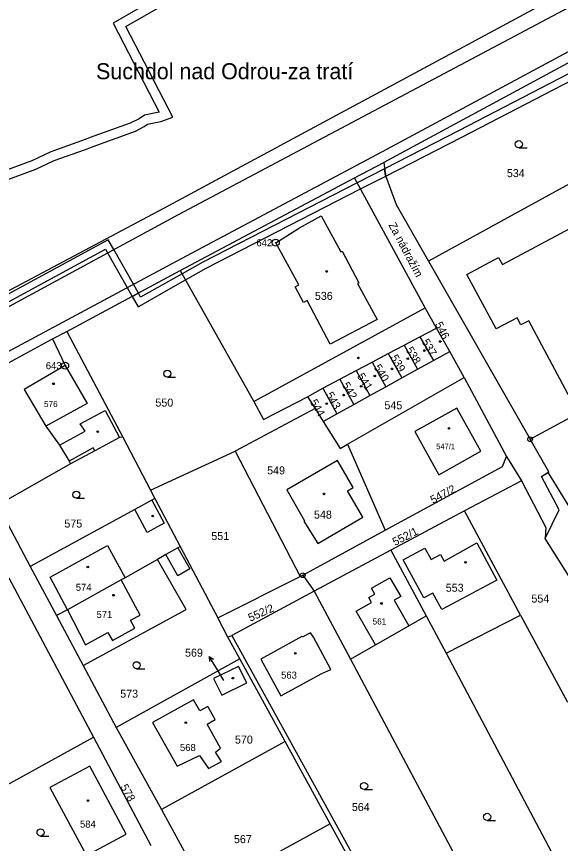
# Model space of a CAD drawing. Extents: x -504988 to -494607, y -1123820 to -1114018.
# Drawn here: x -497582.5 to -497467, y -1121208.2 to -1121032.5 of the extents above; entities that cross this region are included whole.
import ezdxf

# ---------------------------------------------------------------- set-up
doc = ezdxf.new("R2010")
doc.units = 0
for name, color, linetype in [('Hranice parcel', 7, 'Continuous'), ('Parcelní čísla', 7, 'Continuous'), ('Pop  PČ popisy', 7, 'Continuous'), ('Vnitřní kresba', 7, 'Continuous'), ('Věcná břemena k části', 7, 'Continuous'), ('Značky bodu BP', 7, 'Continuous'), ('Značky budov', 7, 'Continuous'), ('Značky kultur', 7, 'Continuous')]:
    doc.layers.add(name, color=color, linetype=linetype)

msp = doc.modelspace()

# ---------------------------------------------------------------- linework, layer by layer
at = {"layer": 'Hranice parcel'}
for p, q in [((-497444.01, -1121056.47), (-497495.04, -1121084.45)), ((-497510.73, -1121066.79), (-497504.55, -1121063.5)), ((-497547.73, -1121086.48), (-497510.73, -1121066.79)), ((-497495.04, -1121084.45), (-497473.48, -1121122.3)), ((-497571.81, -1121099.41), (-497547.73, -1121086.48)), ((-497574.88, -1121100.96), (-497571.81, -1121099.41)), ((-497571.81, -1121099.41), (-497559.93, -1121121.88)), ((-497496.86, -1121100.53), (-497493.36, -1121098.69)), ((-497490.54, -1121103.66), (-497493.36, -1121098.69)), ((-497598.99, -1121114.11), (-497574.88, -1121100.96)), ((-497500.24, -1121102.31), (-497496.86, -1121100.53)), ((-497496.86, -1121100.53), (-497494, -1121105.57)), ((-497503.59, -1121104.09), (-497500.24, -1121102.31)), ((-497500.24, -1121102.31), (-497497.36, -1121107.42)), ((-497507.03, -1121105.91), (-497503.59, -1121104.09)), ((-497503.59, -1121104.09), (-497500.68, -1121109.26)), ((-497494, -1121105.57), (-497490.54, -1121103.66)), ((-497487.47, -1121109.21), (-497490.54, -1121103.66)), ((-497510.43, -1121107.7), (-497507.03, -1121105.91)), ((-497507.03, -1121105.91), (-497504.1, -1121111.15)), ((-497497.36, -1121107.42), (-497494, -1121105.57)), ((-497513.9, -1121109.54), (-497510.43, -1121107.7)), ((-497510.43, -1121107.7), (-497507.47, -1121113.01)), ((-497500.68, -1121109.26), (-497497.36, -1121107.42)), ((-497517.5, -1121111.44), (-497513.9, -1121109.54)), ((-497513.9, -1121109.54), (-497510.91, -1121114.91)), ((-497512.23, -1121123.36), (-497487.47, -1121109.21)), ((-497504.1, -1121111.15), (-497500.68, -1121109.26)), ((-497487.47, -1121109.21), (-497478.53, -1121125.97)), ((-497520.73, -1121113.27), (-497517.5, -1121111.44)), ((-497517.5, -1121111.44), (-497514.49, -1121116.89)), ((-497507.47, -1121113.01), (-497504.1, -1121111.15)), ((-497520.73, -1121113.27), (-497519.14, -1121115.8)), ((-497510.91, -1121114.91), (-497507.47, -1121113.01)), ((-497514.49, -1121116.89), (-497510.91, -1121114.91)), ((-497519.14, -1121115.8), (-497536.09, -1121124.82)), ((-497519.14, -1121115.8), (-497517.43, -1121118.51)), ((-497517.43, -1121118.51), (-497514.49, -1121116.89)), ((-497559.93, -1121121.88), (-497554.06, -1121133.13)), ((-497512.23, -1121123.36), (-497504.22, -1121141.64)), ((-497554.06, -1121133.13), (-497536.09, -1121124.82)), ((-497536.09, -1121124.82), (-497522.28, -1121151.46)), ((-497478.53, -1121125.97), (-497475.34, -1121131.13)), ((-497571.04, -1121127.52), (-497586.5, -1121136.34)), ((-497475.34, -1121131.13), (-497487.42, -1121137.49)), ((-497554.06, -1121133.13), (-497553.13, -1121134.9)), ((-497586.5, -1121136.34), (-497579.58, -1121149.32)), ((-497553.13, -1121134.9), (-497547.79, -1121145.12)), ((-497487.42, -1121137.49), (-497503.02, -1121145.85)), ((-497475.5, -1121159.69), (-497487.42, -1121137.49)), ((-497521.76, -1121151.18), (-497504.22, -1121141.64)), ((-497547.79, -1121145.12), (-497539.75, -1121160.22)), ((-497503.02, -1121145.85), (-497519.35, -1121154.61)), ((-497503.02, -1121145.85), (-497495.55, -1121159.84)), ((-497579.58, -1121149.32), (-497574.03, -1121159.72)), ((-497584.13, -1121151.76), (-497566.16, -1121185.61)), ((-497539.75, -1121160.22), (-497522.28, -1121151.46)), ((-497522.28, -1121151.46), (-497521.76, -1121151.18)), ((-497521.76, -1121151.18), (-497519.35, -1121154.61)), ((-497519.35, -1121154.61), (-497536.83, -1121163.99)), ((-497519.35, -1121154.61), (-497511.59, -1121169.03)), ((-497574.03, -1121159.72), (-497568.35, -1121170.37)), ((-497537.66, -1121164.34), (-497539.75, -1121160.22)), ((-497495.55, -1121159.84), (-497491.31, -1121167.78)), ((-497491.31, -1121167.78), (-497475.5, -1121159.69)), ((-497475.5, -1121159.69), (-497465.57, -1121178.18)), ((-497537.66, -1121164.34), (-497536.83, -1121163.99)), ((-497535.11, -1121168.92), (-497537.66, -1121164.34)), ((-497536.83, -1121163.99), (-497482.55, -1121262.3)), ((-497491.31, -1121167.78), (-497451.07, -1121243.81)), ((-497535.11, -1121168.92), (-497561.32, -1121183.55)), ((-497525.49, -1121186.51), (-497535.11, -1121168.92)), ((-497511.59, -1121169.03), (-497467.06, -1121252.84)), ((-497568.35, -1121170.37), (-497561.32, -1121183.55)), ((-497561.32, -1121183.55), (-497551.74, -1121200.95)), ((-497592.3, -1121200.03), (-497566.16, -1121185.61)), ((-497566.16, -1121185.61), (-497554.01, -1121208.59)), ((-497525.49, -1121186.51), (-497551.74, -1121200.95)), ((-497515.91, -1121204.02), (-497525.49, -1121186.51)), ((-497551.74, -1121200.95), (-497542.24, -1121218.42)), ((-497515.91, -1121204.02), (-497542.24, -1121218.42))]:
    msp.add_line(p, q, dxfattribs=at)
for points in [[(-497161, -1120877.53), (-497162.08, -1120875.61), (-497193.91, -1120893.79), (-497205.64, -1120899.19), (-497240.26, -1120919.63), (-497250.18, -1120924.55), (-497404.22, -1121006.98), (-497504.86, -1121061.28), (-497548.64, -1121084.52), (-497630.65, -1121128.6), (-497742.3, -1121188.23), (-497831.7, -1121236.04), (-497830.39, -1121238.19)], [(-497196.93, -1120886.64), (-497265.24, -1120919.02), (-497346.92, -1120963.08), (-497519.27, -1121056.03), (-497550.25, -1121072.74), (-497642.8, -1121121.95), (-497742.1, -1121178.41), (-497789.44, -1121202.25)], [(-497454.26, -1121037.32), (-497461.19, -1121040.05), (-497504.55, -1121063.5)], [(-497504.55, -1121063.5), (-497504.17, -1121066.25), (-497501.88, -1121072.45), (-497495.04, -1121084.45)], [(-497493.36, -1121098.69), (-497495.78, -1121094.37), (-497510.73, -1121066.79)], [(-497547.73, -1121086.48), (-497532.15, -1121114.3), (-497530.1, -1121118.1), (-497520.73, -1121113.27)], [(-497574.88, -1121100.96), (-497572.18, -1121106.67), (-497580.85, -1121111.75), (-497576.29, -1121119.55), (-497573.34, -1121123.54), (-497571.34, -1121126.99), (-497571.04, -1121127.52)], [(-497473.48, -1121122.3), (-497463.27, -1121116.77), (-497446.25, -1121107.58)], [(-497483.92, -1121124.84), (-497489.04, -1121115.69), (-497497.98, -1121120.68), (-497492.86, -1121129.84), (-497483.92, -1121124.84)], [(-497517.43, -1121118.51), (-497513.81, -1121124.27), (-497512.23, -1121123.36)], [(-497559.93, -1121121.88), (-497560.62, -1121121.95), (-497565.88, -1121124.76), (-497571.04, -1121127.52)], [(-497471.07, -1121130.21), (-497469.54, -1121129.22), (-497473.48, -1121122.3)], [(-497504.22, -1121141.64), (-497479.32, -1121128.1), (-497478.53, -1121125.97)], [(-497518.55, -1121144.48), (-497508.99, -1121138.87), (-497512.24, -1121133.25), (-497511.06, -1121132.57), (-497514.37, -1121126.84), (-497525.15, -1121133.07), (-497521.35, -1121139.64), (-497521.53, -1121139.74), (-497518.55, -1121144.48)], [(-497464.35, -1121137.95), (-497465.39, -1121136.25), (-497469.57, -1121129.41), (-497471.07, -1121130.21)], [(-497475.34, -1121131.13), (-497470.16, -1121141.04), (-497470.26, -1121143.39)], [(-497470.26, -1121143.39), (-497467.32, -1121137.27), (-497471.07, -1121130.21)], [(-497553.13, -1121134.9), (-497553.81, -1121135.27), (-497557.4, -1121137.22), (-497579.58, -1121149.32)], [(-497445.11, -1121171.05), (-497458.87, -1121161.47), (-497470.26, -1121143.39)], [(-497547.79, -1121145.12), (-497548.29, -1121145.36), (-497550.81, -1121146.8), (-497552.55, -1121147.82)], [(-497552.55, -1121147.82), (-497559.42, -1121151.72), (-497560.27, -1121152.19), (-497571.67, -1121158.56), (-497574.03, -1121159.72)], [(-497568.35, -1121170.37), (-497546.52, -1121158.45), (-497552.55, -1121147.82)], [(-497511.59, -1121169.03), (-497506.27, -1121165.98), (-497499.23, -1121161.95), (-497495.55, -1121159.84)], [(-497521.86, -1121164.35), (-497521.93, -1121164.23), (-497530.67, -1121168.99), (-497526.4, -1121176.83), (-497517.66, -1121172.07), (-497515.81, -1121171.19), (-497517.49, -1121168), (-497519.49, -1121164.33), (-497520.07, -1121163.42), (-497521.86, -1121164.35)], [(-497533.64, -1121174.06), (-497535.37, -1121170.55), (-497540.66, -1121173.14), (-497538.94, -1121176.66), (-497533.64, -1121174.06)], [(-497553.64, -1121182.5), (-497548.4, -1121191.75), (-497543.67, -1121189.46), (-497541.76, -1121192.22), (-497539.02, -1121190.77), (-497540.27, -1121188.76), (-497539.19, -1121187.96), (-497542.05, -1121182.83), (-497540.31, -1121181.86), (-497541.88, -1121179.06), (-497543.62, -1121180.03), (-497544.94, -1121177.68), (-497553.64, -1121182.5)], [(-497566.97, -1121191.78), (-497575.41, -1121196.31), (-497567.65, -1121210.75), (-497559.22, -1121206.22), (-497566.97, -1121191.78)], [(-497535.87, -1121230.16), (-497509.45, -1121215.83), (-497515.91, -1121204.02)]]:
    msp.add_lwpolyline(points, dxfattribs=at)
at = {"layer": 'Pop  PČ popisy'}
for p, q in [((-497540.05, -1121170.97), (-497541.64, -1121168.43)), ((-497541.64, -1121168.43), (-497540.68, -1121169.01)), ((-497541.64, -1121168.43), (-497541.53, -1121169.54)), ((-497538.49, -1121173.53), (-497540.05, -1121170.97))]:
    msp.add_line(p, q, dxfattribs=at)
at = {"layer": 'Vnitřní kresba'}
for p, q in [((-497548.12, -1121074.56), (-497415.16, -1121003.88)), ((-497479.34, -1121085.21), (-497447.32, -1121067.97)), ((-497641.18, -1121124.99), (-497548.12, -1121074.56)), ((-497522.45, -1121077.36), (-497517.8, -1121074.86)), ((-497517.8, -1121074.86), (-497513.68, -1121082.52)), ((-497527.47, -1121080.55), (-497522.45, -1121077.36)), ((-497522.59, -1121089.51), (-497527.47, -1121080.55)), ((-497513.68, -1121082.52), (-497513.41, -1121082.38)), ((-497513.41, -1121082.38), (-497509.83, -1121089.05)), ((-497486.94, -1121087.34), (-497480.17, -1121083.68)), ((-497480.17, -1121083.68), (-497479.34, -1121085.21)), ((-497480.68, -1121098.87), (-497486.94, -1121087.34)), ((-497509.83, -1121089.05), (-497510.09, -1121089.19)), ((-497523.36, -1121089.92), (-497522.59, -1121089.51)), ((-497521.57, -1121093.27), (-497523.36, -1121089.92)), ((-497510.09, -1121089.19), (-497505.96, -1121096.86)), ((-497532.15, -1121114.3), (-497495.78, -1121094.37)), ((-497520.79, -1121092.85), (-497521.57, -1121093.27)), ((-497515.89, -1121102.11), (-497520.79, -1121092.85)), ((-497505.96, -1121096.86), (-497515.89, -1121102.11)), ((-497476.26, -1121096.5), (-497480.68, -1121098.87)), ((-497475.44, -1121098.01), (-497476.26, -1121096.5)), ((-497473.72, -1121097.12), (-497475.44, -1121098.01)), ((-497463.27, -1121116.77), (-497473.72, -1121097.12)), ((-497572.18, -1121106.67), (-497567.48, -1121114.7)), ((-497567.48, -1121114.7), (-497576.29, -1121119.55)), ((-497568.96, -1121119), (-497563.71, -1121116.17)), ((-497563.71, -1121116.17), (-497560.62, -1121121.95)), ((-497567.9, -1121120.62), (-497568.96, -1121119)), ((-497573.34, -1121123.54), (-497567.9, -1121120.62)), ((-497566.22, -1121124.11), (-497571.34, -1121126.99)), ((-497565.88, -1121124.76), (-497566.22, -1121124.11)), ((-497553.81, -1121135.27), (-497551.17, -1121140.15)), ((-497554.75, -1121142.1), (-497557.4, -1121137.22)), ((-497551.17, -1121140.15), (-497554.75, -1121142.1)), ((-497575.38, -1121151.59), (-497563.2, -1121144.87)), ((-497563.2, -1121144.87), (-497559.42, -1121151.72)), ((-497548.29, -1121145.36), (-497545.72, -1121149.84)), ((-497491.72, -1121148.18), (-497484.78, -1121144.31)), ((-497484.78, -1121144.31), (-497480.57, -1121152.23)), ((-497548.25, -1121151.29), (-497550.81, -1121146.8)), ((-497500.43, -1121147.95), (-497495.81, -1121145.44)), ((-497495.81, -1121145.44), (-497494.49, -1121147.87)), ((-497494.49, -1121147.87), (-497492.48, -1121146.78)), ((-497492.48, -1121146.78), (-497491.72, -1121148.18)), ((-497496.05, -1121156.02), (-497500.43, -1121147.95)), ((-497545.72, -1121149.84), (-497548.25, -1121151.29)), ((-497571.67, -1121158.56), (-497575.38, -1121151.59)), ((-497556.26, -1121159.65), (-497560.27, -1121152.19)), ((-497507.17, -1121153.96), (-497503.25, -1121151.71)), ((-497503.25, -1121151.71), (-497500.95, -1121155.72)), ((-497480.57, -1121152.23), (-497492.23, -1121158.5)), ((-497506.46, -1121155.21), (-497507.17, -1121153.96)), ((-497507.71, -1121155.93), (-497506.46, -1121155.21)), ((-497507.13, -1121156.95), (-497507.71, -1121155.93)), ((-497500.95, -1121155.72), (-497502.34, -1121156.52)), ((-497494.14, -1121154.98), (-497496.05, -1121156.02)), ((-497492.23, -1121158.5), (-497494.14, -1121154.98)), ((-497510.38, -1121158.81), (-497507.13, -1121156.95)), ((-497502.34, -1121156.52), (-497499.23, -1121161.95)), ((-497571.67, -1121158.56), (-497567.86, -1121165.98)), ((-497506.27, -1121165.98), (-497510.38, -1121158.81)), ((-497558.27, -1121160.75), (-497556.26, -1121159.65)), ((-497557.35, -1121162.44), (-497558.27, -1121160.75)), ((-497562.12, -1121165.09), (-497557.35, -1121162.44)), ((-497567.86, -1121165.98), (-497563.09, -1121163.38)), ((-497563.09, -1121163.38), (-497562.12, -1121165.09))]:
    msp.add_line(p, q, dxfattribs=at)
at = {"layer": 'Věcná břemena k části'}
for points in [[(-497542.08, -1121022.4), (-497561.97, -1121033.92), (-497552.23, -1121052.81), (-497555.31, -1121053.45), (-497556.45, -1121054.2), (-497558.35, -1121055.16), (-497566.12, -1121057.93), (-497568.73, -1121058.94), (-497575.21, -1121061.24), (-497579.23, -1121063.13), (-497589.3, -1121066.84), (-497599.15, -1121071.19), (-497602.98, -1121073.34), (-497606.71, -1121074.35), (-497612.15, -1121076.17), (-497621.14, -1121079.78), (-497629.68, -1121083.55), (-497632.72, -1121085.08), (-497635.95, -1121086.78), (-497652.77, -1121095.06), (-497653.83, -1121095.42)], [(-497588.58, -1121068.71), (-497578.42, -1121064.96), (-497574.5, -1121063.11), (-497568.04, -1121060.81), (-497565.48, -1121059.82), (-497557.27, -1121056.85), (-497555.4, -1121055.89), (-497554.7, -1121055.36), (-497551.87, -1121054.8), (-497549.34, -1121053.89), (-497559.27, -1121034.63), (-497541.24, -1121024.22)]]:
    msp.add_lwpolyline(points, dxfattribs=at)
for points in [[(-497504.36, -1121064.85), (-497504.11, -1121066.4), (-497487.99, -1121058.13), (-497452.88, -1121039.9), (-497453.58, -1121038.58), (-497488.67, -1121056.79)], [(-497509.45, -1121069.14), (-497504.11, -1121066.4), (-497504.17, -1121066.25), (-497504.36, -1121064.85), (-497510.17, -1121067.83), (-497542.94, -1121084.65), (-497547.36, -1121087.15), (-497556.15, -1121092.12), (-497556.63, -1121091.26), (-497557.95, -1121091.97), (-497556.71, -1121094.16), (-497546.62, -1121088.45), (-497542.24, -1121085.97)], [(-497563.03, -1121079.92), (-497621.52, -1121111.63), (-497623.49, -1121111.68), (-497627.01, -1121113.55), (-497621.12, -1121113.12), (-497563.61, -1121081.94), (-497563.17, -1121082.72), (-497559.01, -1121090.09), (-497557.95, -1121091.97), (-497556.63, -1121091.26), (-497557.69, -1121089.38), (-497561.85, -1121082)]]:
    msp.add_lwpolyline(points, close=True, dxfattribs=at)
at = {"layer": 'Značky bodu BP'}
for centre, radius in [((-497527.47, -1121080.55), 0.75), ((-497527.47, -1121080.55), 0.03), ((-497572.18, -1121106.67), 0.75), ((-497572.18, -1121106.67), 0.03), ((-497473.48, -1121122.3), 0.5), ((-497473.48, -1121122.3), 0.0303), ((-497521.76, -1121151.18), 0.5), ((-497521.76, -1121151.18), 0.0303)]:
    msp.add_circle(centre, radius, dxfattribs=at)
at = {"layer": 'Značky budov'}
for centre in [(-497516.65, -1121086.65), (-497492.56, -1121101.54), (-497509.93, -1121105.02), (-497495.92, -1121103.46), (-497499.45, -1121105.2), (-497502.81, -1121107.36), (-497506.46, -1121108.85), (-497574.66, -1121110.52), (-497509.34, -1121111.07), (-497513.06, -1121112.93), (-497516.65, -1121114.73), (-497565.26, -1121120.71), (-497490.7, -1121119.99), (-497517.25, -1121133.91), (-497553.59, -1121138.61), (-497487.2, -1121148.44), (-497567.37, -1121149.46), (-497561.9, -1121155.43), (-497505.03, -1121157.18), (-497523.33, -1121167.77), (-497536.6, -1121173.06), (-497546.57, -1121182.51), (-497567.32, -1121199.06)]:
    msp.add_circle(centre, 0.175, dxfattribs=at)
at = {"layer": 'Značky kultur'}
for p, q in [((-497475.88, -1121060.37), (-497474.13, -1121060.37)), ((-497550.48, -1121109.12), (-497548.73, -1121109.12)), ((-497569.8, -1121134.82), (-497568.05, -1121134.82)), ((-497557.01, -1121171.06), (-497555.26, -1121171.06)), ((-497508.71, -1121196.71), (-497506.96, -1121196.71)), ((-497482.6, -1121203.27), (-497480.85, -1121203.27)), ((-497577.39, -1121206.59), (-497575.64, -1121206.59))]:
    msp.add_line(p, q, dxfattribs=at)
for centre in [(-497475.88, -1121059.62), (-497550.48, -1121108.37), (-497569.8, -1121134.07), (-497557.01, -1121170.31), (-497508.71, -1121195.96), (-497482.6, -1121202.52), (-497577.39, -1121205.84)]:
    msp.add_circle(centre, 0.75, dxfattribs=at)

# ---------------------------------------------------------------- texts
at = {"layer": 'Parcelní čísla'}
for s, height, p in [('534', 1.7, (-497478.42, -1121066.62)), ('536', 1.7, (-497519.17, -1121092.7)), ('550', 1.7, (-497553.02, -1121115.37)), ('576', 1.3, (-497576.67, -1121115.47)), ('545', 1.7, (-497504.41, -1121115.94)), ('547/1', 1.2, (-497493.42, -1121124.42)), ('549', 1.7, (-497529.3, -1121129.77)), ('548', 1.7, (-497519.36, -1121139.16)), ('575', 1.7, (-497572.34, -1121141.07)), ('551', 1.7, (-497541.15, -1121143.71)), ('574', 1.5, (-497569.92, -1121154.5)), ('553', 1.7, (-497491.39, -1121154.7)), ('554', 1.7, (-497473.21, -1121157)), ('571', 1.5, (-497565.51, -1121160.27)), ('561', 1.3, (-497506.92, -1121161.66)), ('569', 1.7, (-497546.73, -1121168.5)), ('563', 1.5, (-497526.34, -1121173.16)), ('573', 1.7, (-497560.49, -1121177.2)), ('570', 1.7, (-497536.14, -1121186.96)), ('568', 1.5, (-497547.8, -1121188.55)), ('564', 1.7, (-497511.32, -1121201.28)), ('584', 1.5, (-497569.02, -1121204.81)), ('567', 1.7, (-497536.35, -1121208.11))]:
    msp.add_text(s, height=height, dxfattribs=at).set_placement(p)
for s, rotation, p in [('546', 297, (-497493.74, -1121097.87)), ('537', 300, (-497496.55, -1121101.57)), ('538', 301, (-497499.94, -1121103.28)), ('539', 299, (-497503.17, -1121104.9)), ('540', 302, (-497506.73, -1121107.03)), ('541', 303, (-497510.29, -1121108.92)), ('542', 301, (-497513.48, -1121110.77)), ('544', 300, (-497520.28, -1121114.4)), ('543', 299, (-497516.89, -1121112.81)), ('547/2', 28, (-497494.12, -1121136.06)), ('552/1', 27, (-497502.16, -1121144.99)), ('552/2', 24, (-497532.87, -1121161.1)), ('578', 299, (-497560.5, -1121196.15))]:
    msp.add_text(s, height=1.7, rotation=rotation, dxfattribs=at).set_placement(p)
at = {"layer": 'Pop  PČ popisy'}
msp.add_text('Suchdol nad Odrou-za tratí', height=3.4, dxfattribs=at).set_placement((-497565.61, -1121045.82))
msp.add_text('Za nádražím', height=1.7, rotation=298, dxfattribs=at).set_placement((-497503.6, -1121076.78))
at = {"layer": 'Značky bodu BP'}
for s, p in [('642', (-497531.57, -1121081.3)), ('643', (-497576.28, -1121107.42))]:
    msp.add_text(s, height=1.5, dxfattribs=at).set_placement(p)

doc.saveas('drawing.dxf')
